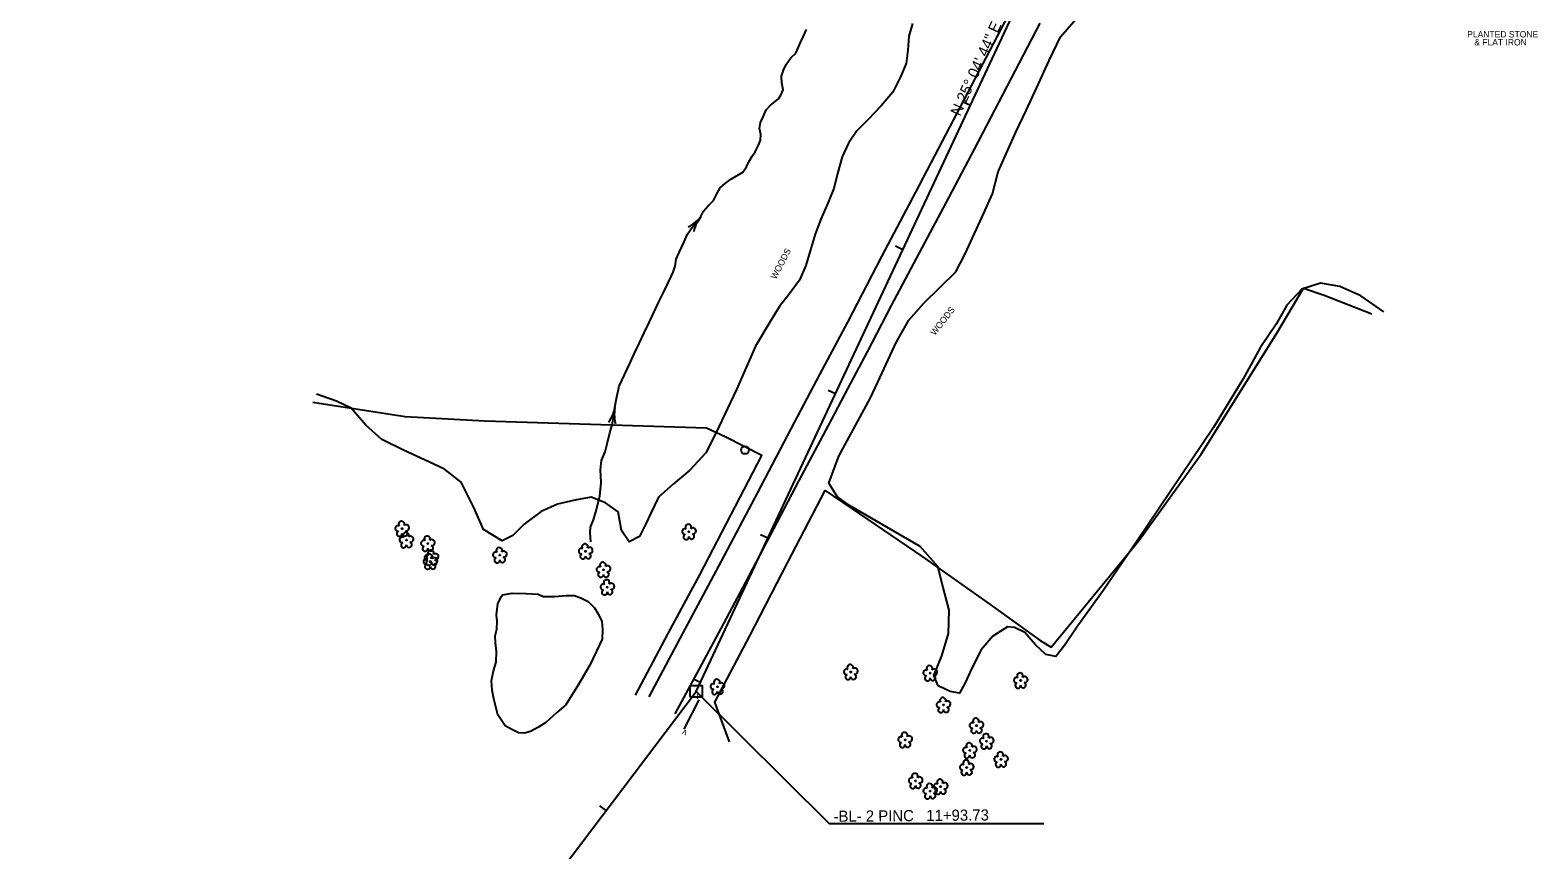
# Model space of a CAD drawing. Extents: x 1149843 to 1151668, y 621784 to 624721.
# Drawn here: x 1149902 to 1150849, y 622299 to 622814 of the extents above; entities that cross this region are included whole.
import ezdxf

# ---------------------------------------------------------------- set-up
doc = ezdxf.new("R2010")
doc.units = 0
for name, color, linetype in [('CTL Supplemental Horizontal and Vertical CELL', 7, 'Continuous'), ('Exist Horizontal Baseline Alignment', 7, 'Continuous'), ('Exist Horizontal Baseline Alignment Direction Label', 7, 'Continuous'), ('Exist Horizontal Baseline Alignment Station Label', 7, 'Continuous'), ('Exist Horizontal Baseline Alignment Tick small', 7, 'Continuous'), ('Exist Hydro Stream Flow Arrow CELL', 7, 'Continuous'), ('Exist Hydro Stream or Body of Water', 7, 'Continuous'), ('Exist Other Culture Fence Line', 7, 'Continuous'), ('Exist Property Iron Pin Text', 7, 'Continuous'), ('Exist Roads EOP', 7, 'Continuous'), ('Exist Structure Minor Culvert Topo', 7, 'Continuous'), ('Exist Structure Minor Culvert Topo Terminator', 7, 'Continuous'), ('Exist Utilities Other Pole CELL', 7, 'Continuous'), ('Exist Vegetation Tree CELL', 7, 'Continuous'), ('Exist Vegetation Woods Line', 7, 'Continuous'), ('Exist Vegetation Woods Line Text', 7, 'Continuous')]:
    doc.layers.add(name, color=color, linetype=linetype)

# ---------------------------------------------------------------- blocks, each defined once
blk = doc.blocks.new('CTL SUPPLEMENTAL HORIZONTAL AND VERTICAL')
at = {"layer": 'CTL Supplemental Horizontal and Vertical CELL'}
blk.add_line((0, 0), (0, 0), dxfattribs=at)
blk.add_lwpolyline([(-0.104, 0), (0.001, 0.105), (0.106, 0), (0.001, -0.105)], close=True, dxfattribs=at)

msp = doc.modelspace()

# ---------------------------------------------------------------- linework, layer by layer
at = {"layer": 'Exist Horizontal Baseline Alignment'}
for p, q in [((1150320.67, 622398.58), (1150617.42, 623032.68)), ((1149902.45, 621845.08), (1150320.67, 622398.58))]:
    msp.add_line(p, q, dxfattribs=at)
at = {"layer": 'Exist Horizontal Baseline Alignment Station Label'}
for p in [(1150320.67, 622398.58), (1150538.94, 622315.33)]:
    msp.add_line(p, (1150404.51, 622315.33), dxfattribs=at)
at = {"layer": 'Exist Horizontal Baseline Alignment Tick small'}
for p, q in [((1150492.87, 622766.55), (1150488.34, 622768.67)), ((1150450.48, 622675.97), (1150445.96, 622678.09)), ((1150408.1, 622585.4), (1150403.57, 622587.52)), ((1150365.71, 622494.83), (1150361.18, 622496.95)), ((1150323.33, 622404.26), (1150318.8, 622406.38)), ((1150264.16, 622323.8), (1150260.17, 622326.81))]:
    msp.add_line(p, q, dxfattribs=at)
at = {"layer": 'Exist Hydro Stream Flow Arrow CELL'}
for p, q in [((1150320.65, 622692.83), (1150320.65, 622692.83)), ((1150268.91, 622572.05), (1150268.91, 622572.05))]:
    msp.add_line(p, q, dxfattribs=at)
for points in [[(1150315.76, 622690.32), (1150317.06, 622691), (1150318.3, 622691.83), (1150319.52, 622692.67), (1150320.64, 622693.59), (1150321.73, 622694.59), (1150322.78, 622695.66), (1150323.74, 622696.76)], [(1150319.35, 622687.49), (1150319.71, 622688.91), (1150320.23, 622690.31), (1150320.76, 622691.7), (1150321.39, 622693), (1150322.1, 622694.29), (1150322.9, 622695.56), (1150323.74, 622696.76)], [(1150265.73, 622567.57), (1150266.57, 622568.77), (1150267.29, 622570.08), (1150267.99, 622571.39), (1150268.56, 622572.72), (1150269.07, 622574.11), (1150269.51, 622575.54), (1150269.86, 622576.96)], [(1150270.22, 622566.71), (1150269.88, 622568.14), (1150269.7, 622569.62), (1150269.53, 622571.09), (1150269.49, 622572.54), (1150269.53, 622574.02), (1150269.66, 622575.51), (1150269.86, 622576.96)]]:
    msp.add_lwpolyline(points, dxfattribs=at)
at = {"layer": 'Exist Hydro Stream or Body of Water'}
for points in [[(1150305.01, 622659.24), (1150306.19, 622661.78), (1150307.43, 622665.56), (1150308.19, 622669.95), (1150310.04, 622674.3), (1150312.92, 622680.51), (1150315.32, 622685.67), (1150317.7, 622689.44), (1150320.65, 622692.83), (1150323.55, 622696.9), (1150325.39, 622700.26), (1150328.29, 622703.6), (1150331.59, 622706.91), (1150333.62, 622710.98), (1150335.82, 622714.9), (1150339.01, 622717.84), (1150342.9, 622720.5), (1150346.35, 622722.67), (1150349.94, 622724.58), (1150352.31, 622728.05), (1150353.8, 622731.24), (1150355.93, 622734.64), (1150357.8, 622737.46), (1150359.73, 622741.59), (1150361.18, 622744.72), (1150361.31, 622748.35), (1150360.37, 622752.17), (1150361.03, 622755.77), (1150362.68, 622759.33), (1150364.73, 622763.74), (1150367.39, 622766.74), (1150372.43, 622770.62), (1150373.95, 622773.08), (1150375.27, 622776.33), (1150374.44, 622780.53), (1150374.2, 622785.01), (1150375.62, 622788.74), (1150377.29, 622792.33), (1150380.06, 622796.41), (1150383.17, 622799.36), (1150384.77, 622802.83), (1150386.27, 622806.05), (1150388.1, 622810), (1150389.02, 622811.99), (1150389.97, 622814.16)], [(1150260.28, 622521.18), (1150260.95, 622529.77), (1150260.62, 622537.75), (1150261.3, 622543.61), (1150263.59, 622549.11), (1150265, 622554.96), (1150266.51, 622560.94), (1150268.16, 622566.83), (1150268.91, 622572.05), (1150269.61, 622577.15), (1150270.83, 622583.6), (1150272.43, 622590.38), (1150275.66, 622597.3), (1150279, 622604.44), (1150282.04, 622610.95), (1150284.91, 622617.09), (1150287.99, 622623.68), (1150291.28, 622630.73), (1150294.22, 622637.02), (1150297.28, 622643.16), (1150300.43, 622649.48), (1150305.01, 622659.24)], [(1150254.55, 622492.53), (1150254.18, 622498.25), (1150254.42, 622501.78), (1150256.15, 622506.43), (1150257.62, 622511.27), (1150260.28, 622521.18)], [(1150197.94, 622457.69), (1150199.09, 622459.17), (1150205.13, 622460.33), (1150213.99, 622460.1), (1150221.47, 622459.6), (1150224.7, 622458.12), (1150231.62, 622458.13), (1150239.03, 622458.92), (1150244.29, 622458.88), (1150248.77, 622457.21), (1150252.93, 622455.07), (1150256.81, 622451.08), (1150259.3, 622446.85), (1150261.52, 622442.57), (1150261.95, 622437.5), (1150261.58, 622431.49), (1150258, 622423.83), (1150253.93, 622415.12), (1150246.78, 622402.9), (1150238.87, 622390.16), (1150233.22, 622385.28), (1150226.3, 622379.14), (1150221.3, 622375.96), (1150217.15, 622373.58), (1150213.15, 622372.41), (1150209.21, 622372.6), (1150204.94, 622374.6), (1150200.69, 622377.04), (1150196.17, 622383.81), (1150195.05, 622387.97), (1150193.54, 622394.02), (1150192.66, 622399.42), (1150192.24, 622405.16), (1150193.36, 622411.43), (1150195.04, 622416.99), (1150195.24, 622423.71), (1150194.72, 622429.39), (1150194.47, 622433.51), (1150195.59, 622437.69), (1150195.63, 622442.77), (1150195.28, 622446.56), (1150195.63, 622450.33), (1150196.09, 622453.59), (1150197.55, 622456.8), (1150197.94, 622457.69)]]:
    msp.add_lwpolyline(points, dxfattribs=at)
at = {"layer": 'Exist Other Culture Fence Line'}
for points in [[(1150598.85, 622493.59), (1150637.74, 622547.55), (1150685.25, 622623.58), (1150702.13, 622651.76), (1150715.02, 622647.46), (1150744.92, 622635.77)], [(1150282.69, 622396.27), (1150303.17, 622434.9), (1150322.94, 622471.88), (1150342.51, 622509.33), (1150362.02, 622546.81), (1150339.33, 622558.17), (1150327.08, 622563.89), (1150188.01, 622568.35), (1150137.88, 622571.11), (1150080, 622579.93)], [(1150341.54, 622366.87), (1150332.41, 622391.82), (1150354.32, 622433.43), (1150378.01, 622479.38), (1150401.78, 622524.86), (1150428.43, 622506.5), (1150462.6, 622483.29), (1150505.25, 622453.25), (1150536.71, 622430.47), (1150543.66, 622426.28), (1150598.85, 622493.59)]]:
    msp.add_lwpolyline(points, dxfattribs=at)
at = {"layer": 'Exist Roads EOP'}
for points in [[(1150519, 622827.67), (1150477.43, 622748.52), (1150458.35, 622712.07), (1150437.12, 622671.76), (1150415.63, 622630.46), (1150398.04, 622597.52)], [(1150416.09, 622589.09), (1150428.35, 622611.82), (1150443.37, 622640.93), (1150460.96, 622674.05), (1150477.59, 622705.36), (1150495.4, 622739.15), (1150536.6, 622818.18)], [(1150398.04, 622597.52), (1150380.12, 622563.41), (1150359.25, 622523.47), (1150336.37, 622480.36), (1150312, 622435.02), (1150291.02, 622395.12)], [(1150307.49, 622384.59), (1150321.33, 622410.02), (1150336.4, 622438.02), (1150351.83, 622467.23), (1150369.37, 622500.65), (1150385.3, 622531.09), (1150403.72, 622565.61), (1150416.09, 622589.09)]]:
    msp.add_lwpolyline(points, dxfattribs=at)
at = {"layer": 'Exist Structure Minor Culvert Topo'}
msp.add_lwpolyline([(1150322.34, 622393.3), (1150313, 622374.87)], dxfattribs=at)
at = {"layer": 'Exist Utilities Other Pole CELL'}
msp.add_circle((1150351.33, 622550.14), 2.46, dxfattribs=at)
at = {"layer": 'Exist Vegetation Tree CELL'}
for p, q in [((1150136.01, 622500.78), (1150136.01, 622500.78)), ((1150316.16, 622498.83), (1150316.16, 622498.83)), ((1150138.73, 622493.61), (1150138.73, 622493.61)), ((1150152.17, 622491.42), (1150152.17, 622491.42)), ((1150251.23, 622486.55), (1150251.23, 622486.55)), ((1150153.73, 622480.05), (1150153.73, 622480.05)), ((1150154.47, 622482.6), (1150154.47, 622482.6)), ((1150197.36, 622484.17), (1150197.36, 622484.17)), ((1150262.47, 622475.02), (1150262.47, 622475.02)), ((1150264.87, 622464.02), (1150264.87, 622464.02)), ((1150417.76, 622410.76), (1150417.76, 622410.76)), ((1150334.01, 622401.51), (1150334.01, 622401.51)), ((1150467.62, 622410.04), (1150467.62, 622410.04)), ((1150524.45, 622405.44), (1150524.45, 622405.44)), ((1150475.99, 622390.08), (1150475.99, 622390.08)), ((1150496.71, 622377.06), (1150496.71, 622377.06)), ((1150451.88, 622368.16), (1150451.88, 622368.16)), ((1150503.06, 622367.27), (1150503.06, 622367.27)), ((1150492.5, 622361.55), (1150492.5, 622361.55)), ((1150512.09, 622355.85), (1150512.09, 622355.85)), ((1150490.56, 622350.77), (1150490.56, 622350.77)), ((1150458.44, 622342.4), (1150458.44, 622342.4)), ((1150467.63, 622335.96), (1150467.63, 622335.96)), ((1150474.18, 622338.77), (1150474.18, 622338.77))]:
    msp.add_line(p, q, dxfattribs=at)
for centre in [(1150136.01, 622500.78), (1150316.16, 622498.83), (1150138.73, 622493.61), (1150152.17, 622491.42), (1150251.23, 622486.55), (1150153.73, 622480.05), (1150154.47, 622482.6), (1150197.36, 622484.17), (1150262.47, 622475.02), (1150264.87, 622464.02), (1150417.76, 622410.76), (1150467.62, 622410.04), (1150334.01, 622401.51), (1150524.45, 622405.44), (1150475.99, 622390.08), (1150496.71, 622377.06), (1150451.88, 622368.16), (1150503.06, 622367.27), (1150492.5, 622361.55), (1150512.09, 622355.85), (1150490.56, 622350.77), (1150458.44, 622342.4), (1150467.63, 622335.96), (1150474.18, 622338.77)]:
    msp.add_circle(centre, 0.326, dxfattribs=at)
for centre, radius, start, end in [((1150135.63, 622503.65), 1.86, 330.16508, 219.71335), ((1150133.41, 622500.93), 1.73, 62.66361, 279.3457), ((1150134.31, 622497.66), 1.69, 111.56708, 6.23104), ((1150136.12, 622493.77), 1.73, 62.66361, 279.3457), ((1150137.69, 622497.88), 1.7, 181.28216, 74.55999), ((1150138.34, 622496.49), 1.86, 330.16508, 219.71335), ((1150138.56, 622501.37), 1.9, 257.1011, 134.19993), ((1150141.28, 622494.2), 1.9, 257.1011, 134.19993), ((1150151.78, 622494.29), 1.86, 330.16508, 219.71335), ((1150313.55, 622498.98), 1.73, 62.66361, 279.3457), ((1150314.45, 622495.71), 1.69, 111.56708, 6.23104), ((1150315.77, 622501.7), 1.86, 330.16508, 219.71335), ((1150317.83, 622495.93), 1.7, 181.28216, 74.55999), ((1150318.71, 622499.41), 1.9, 257.1011, 134.19993), ((1150137.02, 622490.49), 1.69, 111.56708, 6.23104), ((1150140.4, 622490.71), 1.7, 181.28216, 74.55999), ((1150149.56, 622491.57), 1.73, 62.66361, 279.3457), ((1150150.46, 622488.3), 1.69, 111.56708, 6.23104), ((1150153.84, 622488.52), 1.7, 181.28216, 74.55999), ((1150154.09, 622485.47), 1.86, 330.16508, 219.71335), ((1150154.72, 622492.01), 1.9, 257.1011, 134.19993), ((1150194.76, 622484.32), 1.73, 62.66361, 279.3457), ((1150196.98, 622487.04), 1.86, 330.16508, 219.71335), ((1150199.91, 622484.75), 1.9, 257.1011, 134.19993), ((1150248.62, 622486.7), 1.73, 62.66361, 279.3457), ((1150250.84, 622489.42), 1.86, 330.16508, 219.71335), ((1150253.78, 622487.14), 1.9, 257.1011, 134.19993), ((1150151.12, 622480.2), 1.73, 62.66361, 279.3457), ((1150151.87, 622482.75), 1.73, 62.66361, 279.3457), ((1150152.02, 622476.93), 1.69, 111.56708, 6.23104), ((1150152.77, 622479.48), 1.69, 111.56708, 6.23104), ((1150153.34, 622482.92), 1.86, 330.16508, 219.71335), ((1150155.4, 622477.15), 1.7, 181.28216, 74.55999), ((1150156.15, 622479.7), 1.7, 181.28216, 74.55999), ((1150156.28, 622480.64), 1.9, 257.1011, 134.19993), ((1150157.02, 622483.19), 1.9, 257.1011, 134.19993), ((1150195.66, 622481.04), 1.69, 111.56708, 6.23104), ((1150199.04, 622481.27), 1.7, 181.28216, 74.55999), ((1150249.53, 622483.43), 1.69, 111.56708, 6.23104), ((1150252.9, 622483.65), 1.7, 181.28216, 74.55999), ((1150259.86, 622475.18), 1.73, 62.66361, 279.3457), ((1150262.08, 622477.9), 1.86, 330.16508, 219.71335), ((1150265.02, 622475.61), 1.9, 257.1011, 134.19993), ((1150260.76, 622471.9), 1.69, 111.56708, 6.23104), ((1150264.14, 622472.12), 1.7, 181.28216, 74.55999), ((1150264.49, 622466.89), 1.86, 330.16508, 219.71335), ((1150262.27, 622464.17), 1.73, 62.66361, 279.3457), ((1150263.17, 622460.9), 1.69, 111.56708, 6.23104), ((1150266.54, 622461.12), 1.7, 181.28216, 74.55999), ((1150267.42, 622464.6), 1.9, 257.1011, 134.19993), ((1150415.15, 622410.91), 1.73, 62.66361, 279.3457), ((1150417.37, 622413.63), 1.86, 330.16508, 219.71335), ((1150420.3, 622411.35), 1.9, 257.1011, 134.19993), ((1150465.01, 622410.19), 1.73, 62.66361, 279.3457), ((1150467.23, 622412.91), 1.86, 330.16508, 219.71335), ((1150470.17, 622410.63), 1.9, 257.1011, 134.19993), ((1150331.41, 622401.66), 1.73, 62.66361, 279.3457), ((1150333.63, 622404.38), 1.86, 330.16508, 219.71335), ((1150336.56, 622402.1), 1.9, 257.1011, 134.19993), ((1150416.05, 622407.64), 1.69, 111.56708, 6.23104), ((1150419.43, 622407.86), 1.7, 181.28216, 74.55999), ((1150465.91, 622406.92), 1.69, 111.56708, 6.23104), ((1150469.29, 622407.14), 1.7, 181.28216, 74.55999), ((1150521.84, 622405.59), 1.73, 62.66361, 279.3457), ((1150522.74, 622402.32), 1.69, 111.56708, 6.23104), ((1150524.06, 622408.31), 1.86, 330.16508, 219.71335), ((1150526.12, 622402.54), 1.7, 181.28216, 74.55999), ((1150527, 622406.03), 1.9, 257.1011, 134.19993), ((1150332.31, 622398.39), 1.69, 111.56708, 6.23104), ((1150335.69, 622398.61), 1.7, 181.28216, 74.55999), ((1150473.38, 622390.24), 1.73, 62.66361, 279.3457), ((1150475.6, 622392.96), 1.86, 330.16508, 219.71335), ((1150478.54, 622390.67), 1.9, 257.1011, 134.19993), ((1150474.29, 622386.96), 1.69, 111.56708, 6.23104), ((1150477.66, 622387.18), 1.7, 181.28216, 74.55999), ((1150451.5, 622371.04), 1.86, 330.16508, 219.71335), ((1150494.11, 622377.21), 1.73, 62.66361, 279.3457), ((1150495.01, 622373.94), 1.69, 111.56708, 6.23104), ((1150496.33, 622379.93), 1.86, 330.16508, 219.71335), ((1150498.38, 622374.16), 1.7, 181.28216, 74.55999), ((1150499.26, 622377.65), 1.9, 257.1011, 134.19993), ((1150449.27, 622368.32), 1.73, 62.66361, 279.3457), ((1150450.18, 622365.04), 1.69, 111.56708, 6.23104), ((1150453.55, 622365.26), 1.7, 181.28216, 74.55999), ((1150454.43, 622368.75), 1.9, 257.1011, 134.19993), ((1150489.89, 622361.7), 1.73, 62.66361, 279.3457), ((1150492.11, 622364.42), 1.86, 330.16508, 219.71335), ((1150495.05, 622362.14), 1.9, 257.1011, 134.19993), ((1150500.46, 622367.43), 1.73, 62.66361, 279.3457), ((1150501.36, 622364.15), 1.69, 111.56708, 6.23104), ((1150502.68, 622370.15), 1.86, 330.16508, 219.71335), ((1150504.73, 622364.37), 1.7, 181.28216, 74.55999), ((1150505.61, 622367.86), 1.9, 257.1011, 134.19993), ((1150490.18, 622353.65), 1.86, 330.16508, 219.71335), ((1150490.79, 622358.43), 1.69, 111.56708, 6.23104), ((1150494.17, 622358.65), 1.7, 181.28216, 74.55999), ((1150509.49, 622356.01), 1.73, 62.66361, 279.3457), ((1150510.39, 622352.73), 1.69, 111.56708, 6.23104), ((1150511.71, 622358.73), 1.86, 330.16508, 219.71335), ((1150513.77, 622352.95), 1.7, 181.28216, 74.55999), ((1150514.64, 622356.44), 1.9, 257.1011, 134.19993), ((1150455.84, 622342.55), 1.73, 62.66361, 279.3457), ((1150458.06, 622345.27), 1.86, 330.16508, 219.71335), ((1150460.99, 622342.98), 1.9, 257.1011, 134.19993), ((1150487.96, 622350.93), 1.73, 62.66361, 279.3457), ((1150488.86, 622347.65), 1.69, 111.56708, 6.23104), ((1150492.23, 622347.87), 1.7, 181.28216, 74.55999), ((1150493.11, 622351.36), 1.9, 257.1011, 134.19993), ((1150456.74, 622339.28), 1.69, 111.56708, 6.23104), ((1150460.12, 622339.5), 1.7, 181.28216, 74.55999), ((1150465.02, 622336.12), 1.73, 62.66361, 279.3457), ((1150467.25, 622338.84), 1.86, 330.16508, 219.71335), ((1150469.3, 622333.06), 1.7, 181.28216, 74.55999), ((1150470.18, 622336.55), 1.9, 257.1011, 134.19993), ((1150471.57, 622338.92), 1.73, 62.66361, 279.3457), ((1150472.48, 622335.65), 1.69, 111.56708, 6.23104), ((1150473.79, 622341.64), 1.86, 330.16508, 219.71335), ((1150475.85, 622335.87), 1.7, 181.28216, 74.55999), ((1150476.73, 622339.36), 1.9, 257.1011, 134.19993), ((1150465.93, 622332.84), 1.69, 111.56708, 6.23104)]:
    msp.add_arc(centre, radius, start, end, dxfattribs=at)
at = {"layer": 'Exist Vegetation Woods Line'}
for points in [[(1150456.58, 622817.93), (1150454.19, 622810.03), (1150453.54, 622801.24), (1150452.54, 622792.81), (1150449, 622784.51), (1150444.11, 622774.92), (1150436.88, 622766.36), (1150428.75, 622757.82), (1150421.52, 622750.65), (1150416.42, 622742.85), (1150412.41, 622734.2), (1150409.53, 622723.73), (1150407.22, 622714.3), (1150403.44, 622705.14), (1150399.06, 622695.16), (1150395.46, 622685.8), (1150392.23, 622675.16), (1150389.54, 622666.1), (1150385.58, 622656.87), (1150379.16, 622648.13), (1150372.95, 622640.27), (1150367.61, 622631.51), (1150357.96, 622615.31)], [(1150430.12, 622582.93), (1150437.42, 622598.69), (1150446.23, 622617.68), (1150454.26, 622631.78), (1150463.66, 622642.34), (1150473.77, 622652.26), (1150483.84, 622662.12), (1150489.54, 622673.44), (1150495.4, 622686.09), (1150501.38, 622698.98), (1150506.84, 622711), (1150510.31, 622724.82), (1150516.18, 622738.15), (1150521.52, 622749.69), (1150527.84, 622763.32), (1150534.55, 622777.79), (1150542.43, 622794.79), (1150549.37, 622809.75), (1150561.94, 622824.09)], [(1150752.59, 622637.02), (1150738.05, 622647.04), (1150724.94, 622652.91), (1150712.64, 622654.95), (1150701.1, 622651.26), (1150691.66, 622641.24), (1150684.93, 622629.27), (1150674.85, 622614.31), (1150664.25, 622594.96), (1150645.61, 622564.25), (1150597.7, 622493.1)], [(1150357.96, 622615.31), (1150345.94, 622588.24), (1150338.45, 622572.2), (1150333.54, 622561.69), (1150326.78, 622548.51), (1150316.69, 622537.56), (1150306.16, 622528.67), (1150296.95, 622520.6), (1150292.23, 622510.51), (1150289.09, 622503.81), (1150285.12, 622495.79), (1150278.54, 622492.51), (1150273.85, 622499.61), (1150271.76, 622511.31), (1150263.77, 622517.07), (1150254.79, 622520.55), (1150244.45, 622518.74), (1150233.53, 622516.23), (1150223.32, 622511.48), (1150212.7, 622503.61), (1150205.58, 622496.46), (1150198.88, 622493.08), (1150187.14, 622500.37), (1150181.14, 622514.02), (1150173.14, 622530.01), (1150162.61, 622538.11), (1150150.07, 622543.96), (1150136.86, 622550.14), (1150123.24, 622556.7), (1150113.24, 622565.85), (1150104, 622576.47), (1150094.77, 622580.8), (1150082.37, 622585.18)], [(1150597.7, 622493.1), (1150576.42, 622462.17), (1150559.7, 622439.01), (1150552.05, 622427.47), (1150546.47, 622420.46), (1150540.34, 622421.72), (1150533.68, 622427.88), (1150527.01, 622435.58), (1150520.59, 622438.77), (1150516.16, 622439.05), (1150506.97, 622433.34), (1150499.67, 622424.62), (1150493.63, 622412.76), (1150489.52, 622403.95), (1150485.98, 622397.54), (1150480.13, 622398.53), (1150472.58, 622402.07), (1150470.02, 622408.59), (1150475.01, 622420.87), (1150479.18, 622435), (1150479.47, 622449.53), (1150475.84, 622463.87), (1150472.53, 622477.02), (1150461.43, 622489.69), (1150417, 622515.28), (1150409.17, 622521.01), (1150404.03, 622529.41), (1150410.3, 622546.27), (1150430.12, 622582.93)]]:
    msp.add_lwpolyline(points, dxfattribs=at)

# ---------------------------------------------------------------- block references
at = {"layer": 'CTL Supplemental Horizontal and Vertical CELL', "xscale": 50, "yscale": 49.99999999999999, "rotation": 44.99999999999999}
msp.add_blockref('CTL SUPPLEMENTAL HORIZONTAL AND VERTICAL', (1150320.67, 622398.58), dxfattribs=at)

# ---------------------------------------------------------------- texts
at = {"layer": 'Exist Horizontal Baseline Alignment Direction Label'}
msp.add_text('N 25%%d 04\' 44" E', height=7, rotation=65.53349, dxfattribs=at).set_placement((1150486.32, 622759.41))
at = {"layer": 'Exist Horizontal Baseline Alignment Station Label'}
msp.add_text('-BL- 2 PINC   11+93.73 ', height=7, rotation=0.51392, dxfattribs=at).set_placement((1150406.97, 622316.66))
at = {"layer": 'Exist Property Iron Pin Text'}
for s, p in [('PLANTED STONE', (1150804.87, 622809.25)), ('& FLAT IRON', (1150809.3, 622804.24))]:
    msp.add_text(s, height=4, rotation=0.00002, dxfattribs=at).set_placement(p)
at = {"layer": 'Exist Structure Minor Culvert Topo Terminator'}
for rotation, p in [(332.88105, (1150319.98, 622394.51)), (153.36275, (1150315.36, 622373.69))]:
    msp.add_text('v', height=4, rotation=rotation, dxfattribs=at).set_placement(p)
at = {"layer": 'Exist Vegetation Woods Line Text'}
for rotation, p in [(62.53108, (1150370.81, 622657.04)), (52.13154, (1150470.65, 622621.78))]:
    msp.add_text('WOODS', height=4, rotation=rotation, dxfattribs=at).set_placement(p)

doc.saveas('drawing.dxf')
